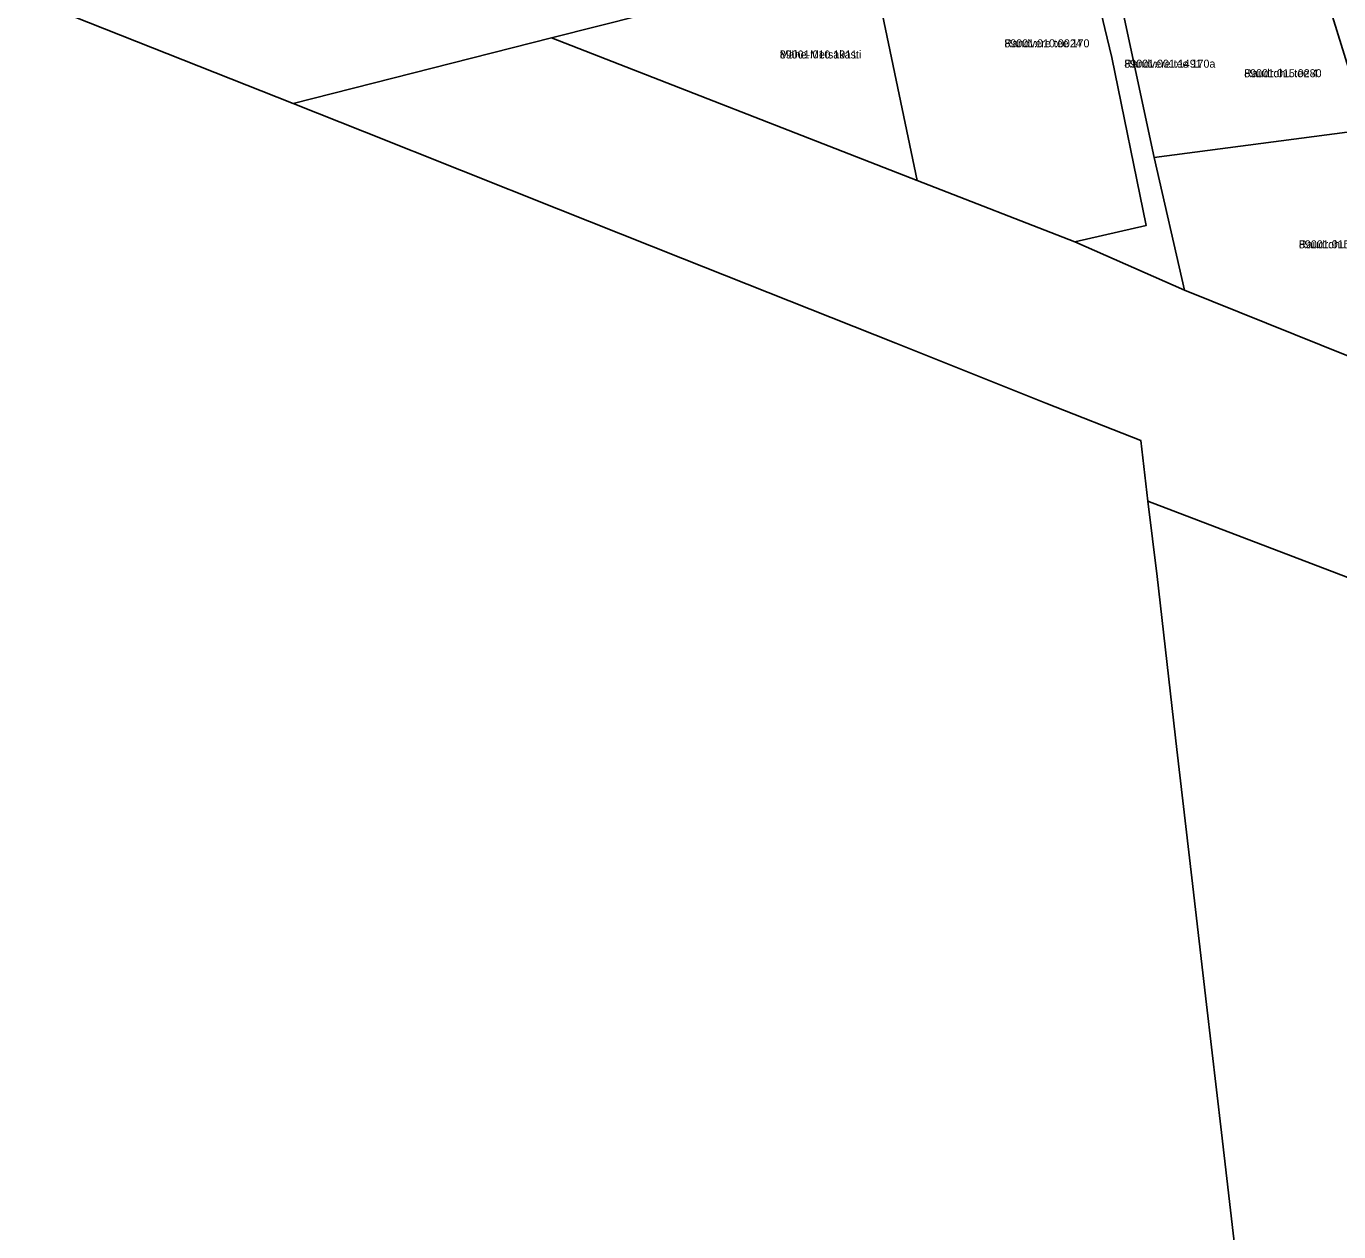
# Model space of a CAD drawing. Extents: x 526849 to 562296, y 6591741 to 6618546.
# Drawn here: x 550135.5 to 550381.5, y 6594978.5 to 6595204.6 of the extents above; entities that cross this region are included whole.
import ezdxf

# ---------------------------------------------------------------- set-up
doc = ezdxf.new("R2010")
doc.units = 0
for name, color, linetype in [('L_AADRESS', 7, 'Continuous'), ('PIIR', 7, 'Continuous'), ('TUNNUS', 7, 'Continuous')]:
    doc.layers.add(name, color=color, linetype=linetype)

msp = doc.modelspace()

# ---------------------------------------------------------------- linework, layer by layer
at = {"layer": 'PIIR'}
for points in [[(550412.29, 6595255.21), (550379.75, 6595247.75), (550370.12, 6595245.41), (550334.08, 6595236), (550330.01, 6595235.1), (550292.23, 6595224.49), (550293.71, 6595217.55), (550233.97, 6595202.37), (550185.55, 6595190.06), (550135.5, 6595209.95), (550187.67, 6595221.58), (550238.41, 6595235.4), (550305.29, 6595253.63), (550376.95, 6595273.16), (550385.87, 6595275.93)], [(550386.86, 6595185.21), (550379.19, 6595210.08), (550370.12, 6595245.41), (550379.75, 6595247.75), (550389.59, 6595212.94)], [(550456.5, 6595073.2), (550345.73, 6595115.5), (550344.4, 6595126.89), (550326.57, 6595133.91), (550298.47, 6595145.15), (550278.51, 6595153.09), (550258.5, 6595161.05), (550235.24, 6595170.3), (550217.05, 6595177.53), (550198.89, 6595184.75), (550185.55, 6595190.06), (550233.97, 6595202.37), (550302.47, 6595175.66), (550331.99, 6595164.15), (550352.56, 6595155.1), (550388.41, 6595140.65)]]:
    msp.add_lwpolyline(points, dxfattribs=at)
for points in [[(550346.9, 6595179.94), (550352.56, 6595155.1), (550331.99, 6595164.15), (550345.4, 6595167.23), (550338.98, 6595198.73), (550337.66, 6595204.17), (550331.78, 6595228.82), (550330.01, 6595235.1), (550334.08, 6595236), (550341.16, 6595206.77)], [(550293.71, 6595217.55), (550292.23, 6595224.49), (550330.01, 6595235.1), (550331.78, 6595228.82), (550337.66, 6595204.17), (550338.98, 6595198.73), (550345.4, 6595167.23), (550331.99, 6595164.15), (550302.47, 6595175.66)], [(550233.97, 6595202.37), (550293.71, 6595217.55), (550302.47, 6595175.66)], [(550341.16, 6595206.77), (550379.19, 6595210.08), (550386.86, 6595185.21), (550346.9, 6595179.94)], [(550352.56, 6595155.1), (550346.9, 6595179.94), (550386.86, 6595185.21), (550403.78, 6595179.32), (550388.41, 6595140.65)], [(550345.73, 6595115.5), (550456.5, 6595073.2), (550452.87, 6595044.72), (550491.99, 6594854.78), (550396, 6594803.35), (550381.76, 6594806.29), (550378.04, 6594838.2), (550375.15, 6594862.96), (550372.24, 6594887.91), (550369.29, 6594913.28), (550366.45, 6594937.55), (550365.36, 6594946.97), (550365.07, 6594949.45), (550362.2, 6594973.93), (550359.5, 6594997.12), (550356.71, 6595021.13), (550353.93, 6595044.9), (550351.12, 6595068.93), (550347.45, 6595101.38)]]:
    msp.add_lwpolyline(points, close=True, dxfattribs=at)

# ---------------------------------------------------------------- texts
at = {"layer": 'L_AADRESS'}
for s, p in [('Randvere tee 170', (550318.81, 6595200.62)), ('Mähe-Metsakasti', (550276.72, 6595198.53)), ('Randvere tee 170a', (550341.29, 6595196.8)), ('Raudrohu tee 4', (550363.76, 6595195.01)), ('Raudrohu tee 6', (550374.02, 6595162.93))]:
    msp.add_text(s, height=1.5, dxfattribs=at).set_placement(p)
at = {"layer": 'TUNNUS'}
for s, p in [('89001:010:0024', (550318.81, 6595200.62)), ('89001:010:1911', (550276.72, 6595198.53)), ('89001:001:1491', (550341.29, 6595196.8)), ('89001:015:0280', (550363.76, 6595195.01)), ('89001:015:0290', (550374.02, 6595162.93))]:
    msp.add_text(s, height=1.5, dxfattribs=at).set_placement(p)

doc.saveas('drawing.dxf')
